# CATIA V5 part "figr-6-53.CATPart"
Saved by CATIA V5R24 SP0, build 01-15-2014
Part number: Part1
Bounding box of the stored display mesh (mm): x -46.66 to 43.071, y -43.071 to 47.059, z 0 to 20
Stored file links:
  D:\KAVITA\CATIA V5-6R2014 Project_ Kavita\CATIA V5-6R2014_partfiles\Partfiles\c06_catia_v5-6r2014_prt\figr-6-53.CATPart
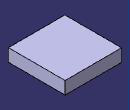
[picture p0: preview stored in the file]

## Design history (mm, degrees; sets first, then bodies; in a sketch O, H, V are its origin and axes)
Body1 (main body)
  Sketch1 on xy-plane, origin (0, 0, 0), H (1, 0, 0), V (0, 1, 0)
    line L1 (-46.6598, 47.0586) -> (43.0706, 47.0586)
    line L2 (43.0706, 47.0586) -> (43.0706, -43.0706)
    line L3 (43.0706, -43.0706) -> (-46.6598, -43.0706)
    line L4 (-46.6598, -43.0706) -> (-46.6598, 47.0586)
    horizontal: L1 H, L3 H
    vertical: L2 V, L4 V
  Pad1: profile Sketch1, direction (0, 0, 1), length 20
